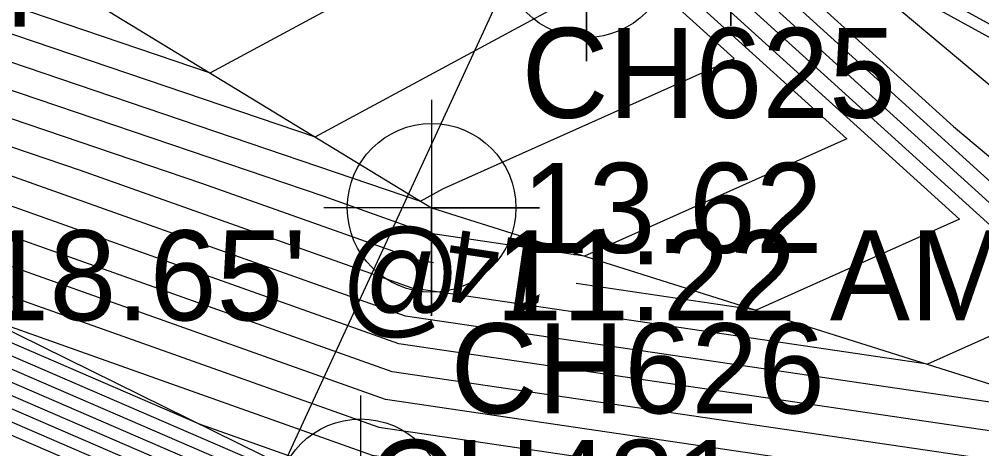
# Model space of a CAD drawing. Extents: x 2531902 to 2533249, y 715219 to 716099.
# Drawn here: x 2532867.85 to 2532894.6, y 715624.97 to 715636.9 of the extents above; entities that cross this region are included whole.
import ezdxf

# ---------------------------------------------------------------- set-up
doc = ezdxf.new("R2010")
doc.units = 0
for name, color, linetype in [('DTM Contours Major', 7, 'Continuous'), ('DTM Contours Major Text', 7, 'Continuous'), ('DTM Contours Minor', 7, 'Continuous'), ('Exist DTM Breakline Cogo Number', 7, 'Continuous'), ('Exist DTM Breakline Underwater', 7, 'Continuous'), ('Exist DTM Breakline Underwater Cogo Number', 7, 'Continuous'), ('Exist DTM Breakline Underwater Cogo Point CELL', 7, 'Continuous'), ('Exist DTM Drainline', 7, 'Continuous'), ('Exist DTM Drainline Cogo Elevation', 7, 'Continuous'), ('Exist DTM Drainline Cogo Number', 7, 'Continuous'), ('Exist DTM Drainline Cogo Point CELL', 7, 'Continuous'), ('Exist DTM Regular Point Underwater CELL', 7, 'Continuous'), ('Exist DTM Spot Elevation Cogo Comment', 7, 'Continuous'), ('Exist Structure Major Deck Tunnel Box Culvert', 7, 'Continuous')]:
    doc.layers.add(name, color=color, linetype=linetype)

msp = doc.modelspace()

# ---------------------------------------------------------------- linework, layer by layer
at = {"layer": 'DTM Contours Major'}
for points in [[(2532856.997, 715637.752), (2532843.634, 715642.154), (2532838.95, 715642.446), (2532837.196, 715642.916), (2532836.212, 715643.844), (2532838.777, 715646.373), (2532845.302, 715648.224), (2532849.017, 715650.08), (2532864.862, 715652.703), (2532871.849, 715648.562), (2532884.074, 715640.066), (2532885.362, 715639.162), (2532893.985, 715631.35), (2532888.331, 715628.819), (2532883.327, 715629.556)], [(2532890.655, 715638.312), (2532891.571, 715637.809), (2532905.569, 715626.076), (2532912.721, 715621.73), (2532926.519, 715615.888), (2532945.44, 715606.058), (2532953.026, 715604.623), (2532954.038, 715604.431), (2532959.139, 715598.483), (2532956.246, 715598.192), (2532949.44, 715599.203), (2532945.9, 715601.139), (2532940.376, 715602.093)], [(2532817.128, 715638.01), (2532821.44, 715633.942), (2532823.39, 715631.913), (2532822.855, 715631.652), (2532823.68, 715631.826), (2532823.763, 715631.845), (2532823.772, 715631.846), (2532823.783, 715631.864), (2532823.783, 715631.864), (2532835.752, 715634.822), (2532835.755, 715634.82), (2532836.696, 715634.236), (2532839.231, 715634.075), (2532839.687, 715634.047), (2532853.186, 715633.24), (2532854.851, 715632.85), (2532855.116, 715632.593), (2532856.394, 715632.04), (2532875.724, 715623.687), (2532877.133, 715623.117), (2532877.381, 715623.013)], [(2532879.37, 715630.138), (2532878.964, 715630.198), (2532872.928, 715632.341), (2532856.997, 715637.752)], [(2532780.658, 715624.297), (2532785.254, 715624.315), (2532796.252, 715624.232), (2532796.808, 715624.228), (2532797.67, 715624.41), (2532814.677, 715628), (2532824.557, 715630.182), (2532825.526, 715630.396), (2532826.886, 715632.485), (2532826.893, 715632.496), (2532834.338, 715634.336), (2532834.344, 715634.332), (2532836.264, 715633.141), (2532841.438, 715632.811), (2532842.37, 715632.755), (2532850.775, 715632.253), (2532854.159, 715631.46), (2532854.698, 715630.937), (2532857.296, 715629.814), (2532869.332, 715624.613), (2532876.125, 715621.862)], [(2532936.434, 715602.773), (2532934.742, 715603.065), (2532933.508, 715601.95), (2532924.263, 715605.674), (2532923.807, 715605.858), (2532922.059, 715606.587), (2532911.346, 715610.569), (2532910.592, 715612.891), (2532904.159, 715618.856), (2532896.829, 715623.571), (2532878.035, 715626.337), (2532856.052, 715634.14), (2532855.566, 715634.305)]]:
    msp.add_lwpolyline(points, dxfattribs=at)
at = {"layer": 'DTM Contours Minor'}
for points in [[(2532856.138, 715635.684), (2532850.548, 715637.525), (2532837.888, 715638.314), (2532833.147, 715639.585), (2532830.487, 715642.094), (2532837.419, 715648.929), (2532840.402, 715649.776), (2532842.1, 715650.624), (2532855.971, 715652.92), (2532864.607, 715654.041), (2532865.23, 715654.258), (2532865.541, 715653.902), (2532865.615, 715653.875), (2532865.688, 715653.855), (2532865.833, 715653.77), (2532866.572, 715653.426), (2532867.856, 715652.83), (2532884.49, 715641.268), (2532886.945, 715639.546), (2532903.381, 715624.656), (2532902.622, 715624.317), (2532878.406, 715627.882), (2532862.803, 715633.42), (2532856.138, 715635.684)], [(2532856.424, 715636.373), (2532848.243, 715639.068), (2532838.242, 715639.691), (2532834.497, 715640.695), (2532832.395, 715642.678), (2532837.872, 715648.077), (2532842.035, 715649.258), (2532844.406, 715650.442), (2532863.769, 715653.648), (2532865.381, 715653.857), (2532865.497, 715653.897), (2532865.555, 715653.831), (2532865.569, 715653.826), (2532865.583, 715653.822), (2532865.61, 715653.806), (2532865.748, 715653.742), (2532865.987, 715653.631), (2532884.352, 715640.868), (2532886.417, 715639.418), (2532900.249, 715626.888), (2532897.858, 715625.818), (2532878.592, 715628.654), (2532866.178, 715633.06), (2532856.424, 715636.373)], [(2532856.71, 715637.063), (2532845.938, 715640.611), (2532838.596, 715641.069), (2532835.846, 715641.806), (2532834.303, 715643.261), (2532838.324, 715647.225), (2532843.668, 715648.741), (2532846.711, 715650.261), (2532865.255, 715653.331), (2532868.296, 715651.529), (2532884.213, 715640.467), (2532885.89, 715639.29), (2532897.117, 715629.119), (2532893.094, 715627.318), (2532878.778, 715629.426), (2532869.553, 715632.7), (2532856.71, 715637.063)], [(2532857.283, 715638.441), (2532841.329, 715643.697), (2532839.304, 715643.823), (2532838.546, 715644.026), (2532838.12, 715644.428), (2532839.229, 715645.521), (2532846.935, 715647.707), (2532851.323, 715649.899), (2532864.469, 715652.075), (2532875.402, 715645.596), (2532883.935, 715639.665), (2532884.834, 715639.034), (2532890.854, 715633.581), (2532883.567, 715630.32), (2532879.149, 715630.97), (2532876.303, 715631.981), (2532857.283, 715638.441)], [(2532879.001, 715631.851), (2532879.641, 715632.196), (2532887.722, 715635.812), (2532884.307, 715638.906), (2532883.796, 715639.264), (2532878.955, 715642.629), (2532864.076, 715651.447), (2532853.629, 715649.717), (2532848.568, 715647.19), (2532840.26, 715644.833), (2532857.569, 715639.131), (2532879.001, 715631.851)], [(2532876.079, 715633.63), (2532882.671, 715637.185), (2532884.59, 715638.043), (2532883.779, 715638.778), (2532883.658, 715638.863), (2532882.508, 715639.663), (2532863.682, 715650.819), (2532855.935, 715649.536), (2532850.202, 715646.673), (2532843.137, 715644.669), (2532857.855, 715639.82), (2532876.079, 715633.63)], [(2532880.52, 715639.379), (2532877.948, 715641.504), (2532863.289, 715650.191), (2532858.241, 715649.355), (2532851.835, 715646.156), (2532846.014, 715644.505), (2532858.141, 715640.51), (2532873.157, 715635.409), (2532880.52, 715639.379)], [(2532975.24, 715591.229), (2532960.443, 715606.627), (2532958.703, 715607.649), (2532957.75, 715608.02), (2532955.613, 715608.719), (2532955.6, 715608.723), (2532955.419, 715608.782), (2532944.262, 715612.427), (2532932.72, 715614.61), (2532927.096, 715617.532), (2532922.994, 715619.269), (2532906.523, 715629.277), (2532902.833, 715632.37), (2532888.074, 715640.47)], [(2532809.568, 715640.234), (2532811.222, 715636.857), (2532814.753, 715633.181), (2532801.65, 715626.79), (2532821.879, 715631.061), (2532823.922, 715631.512), (2532824.122, 715631.556), (2532824.404, 715631.988), (2532824.405, 715631.991), (2532835.469, 715634.724), (2532835.473, 715634.722), (2532836.609, 715634.017), (2532839.672, 715633.822), (2532840.224, 715633.789), (2532852.704, 715633.043), (2532854.713, 715632.572), (2532855.033, 715632.261), (2532856.575, 715631.595), (2532874.446, 715623.872), (2532876.969, 715622.851), (2532878.852, 715622.065), (2532899.232, 715613.375)], [(2532824.761, 715640.344), (2532829.098, 715636.253), (2532834.857, 715634.71), (2532836.883, 715635.21), (2532836.884, 715635.21), (2532837.041, 715635.113), (2532837.465, 715635.085), (2532837.541, 715635.081), (2532855.115, 715634.03), (2532855.404, 715633.962), (2532855.45, 715633.917), (2532855.673, 715633.821), (2532860.659, 715631.667), (2532877.849, 715625.565), (2532891.612, 715623.539), (2532903.717, 715615.754)], [(2532897.202, 715635.09), (2532887.91, 715640.189)], [(2532822.853, 715639.76), (2532827.748, 715635.143), (2532832.052, 715633.989), (2532836.6, 715635.113), (2532836.601, 715635.113), (2532836.955, 715634.894), (2532837.906, 715634.833), (2532838.078, 715634.822), (2532854.632, 715633.833), (2532855.266, 715633.684), (2532855.367, 715633.586), (2532855.853, 715633.376), (2532866.757, 715628.664), (2532877.663, 715624.793), (2532886.395, 715623.508), (2532901.833, 715613.579)], [(2532887.473, 715639.673), (2532893.82, 715633.924), (2532905.092, 715624.475), (2532907.585, 715622.961), (2532926.231, 715615.065), (2532950.587, 715602.412), (2532932.324, 715605.565), (2532930.175, 715603.621), (2532924.087, 715606.074), (2532923.787, 715606.195), (2532922.636, 715606.675), (2532915.581, 715609.297), (2532914.43, 715612.845), (2532904.601, 715621.959), (2532902.046, 715623.602), (2532878.22, 715627.11), (2532859.428, 715633.78), (2532855.852, 715634.994)], [(2532820.944, 715639.177), (2532826.399, 715634.032), (2532829.247, 715633.269), (2532836.318, 715635.016), (2532836.319, 715635.015), (2532836.868, 715634.675), (2532838.348, 715634.58), (2532838.614, 715634.564), (2532854.15, 715633.635), (2532855.128, 715633.406), (2532855.283, 715633.255), (2532856.034, 715632.931), (2532872.855, 715625.662), (2532877.477, 715624.021), (2532881.178, 715623.476), (2532887.721, 715619.268), (2532902.221, 715613.085)], [(2532819.036, 715638.593), (2532825.049, 715632.922), (2532826.442, 715632.549), (2532836.035, 715634.919), (2532836.037, 715634.917), (2532836.782, 715634.455), (2532838.789, 715634.327), (2532839.151, 715634.306), (2532853.668, 715633.438), (2532854.989, 715633.128), (2532855.2, 715632.924), (2532856.214, 715632.486), (2532877.003, 715623.502), (2532877.297, 715623.383), (2532877.517, 715623.291), (2532901.224, 715613.182)], [(2532796.887, 715625.399), (2532820.079, 715630.296), (2532824.081, 715631.18), (2532824.473, 715631.266), (2532825.024, 715632.113), (2532825.027, 715632.117), (2532835.187, 715634.627), (2532835.191, 715634.625), (2532836.523, 715633.798), (2532840.114, 715633.569), (2532840.76, 715633.53), (2532852.221, 715632.845), (2532854.574, 715632.294), (2532854.949, 715631.93), (2532856.755, 715631.15), (2532873.167, 715624.058), (2532876.804, 715622.584), (2532879.519, 715621.452), (2532898.235, 715613.471)], [(2532797.148, 715625.069), (2532818.278, 715629.531), (2532824.24, 715630.847), (2532824.824, 715630.976), (2532825.645, 715632.237), (2532825.649, 715632.243), (2532834.904, 715634.53), (2532834.909, 715634.527), (2532836.437, 715633.579), (2532840.555, 715633.316), (2532841.297, 715633.272), (2532851.739, 715632.648), (2532854.436, 715632.016), (2532854.866, 715631.599), (2532856.935, 715630.705), (2532871.889, 715624.243), (2532876.64, 715622.318), (2532880.187, 715620.839), (2532897.239, 715613.567)], [(2532797.409, 715624.739), (2532816.477, 715628.766), (2532824.398, 715630.515), (2532825.175, 715630.686), (2532826.265, 715632.361), (2532826.271, 715632.37), (2532834.621, 715634.433), (2532834.627, 715634.43), (2532836.35, 715633.36), (2532840.997, 715633.064), (2532841.834, 715633.014), (2532851.257, 715632.45), (2532854.298, 715631.738), (2532854.782, 715631.268), (2532857.116, 715630.259), (2532870.61, 715624.428), (2532876.476, 715622.052), (2532880.854, 715620.226), (2532896.243, 715613.664)]]:
    msp.add_lwpolyline(points, dxfattribs=at)
at = {"layer": 'Exist DTM Breakline Underwater'}
msp.add_lwpolyline([(2532642.404, 715750.56), (2532658.799, 715717.787), (2532669.356, 715695.376), (2532679.885, 715666.767), (2532697.228, 715643.446), (2532713.346, 715638.817), (2532732.829, 715632.464), (2532756.843, 715626.148), (2532779.072, 715626.28), (2532796.688, 715625.652), (2532823.757, 715631.859), (2532837.11, 715635.289), (2532855.521, 715634.196), (2532877.341, 715623.453), (2532903.322, 715612.979), (2532923.748, 715606.844), (2532938.002, 715599.697), (2532947.164, 715595.611), (2532973.382, 715584.595), (2532998.348, 715572.794), (2533019.077, 715559.415)], dxfattribs=at)
at = {"layer": 'Exist DTM Breakline Underwater Cogo Point CELL'}
msp.add_lwpolyline([(2532877.341, 715626.453), (2532877.341, 715620.453), (2532877.341, 715623.453), (2532880.341, 715623.453), (2532874.341, 715623.453)], dxfattribs=at)
msp.add_circle((2532877.341, 715623.453), 2.344, dxfattribs=at)
at = {"layer": 'Exist DTM Drainline'}
msp.add_lwpolyline([(2532712.089, 715642.317), (2532734.218, 715637.287), (2532753.576, 715632.211), (2532781.659, 715633.208), (2532801.91, 715635.068), (2532816.971, 715637.962), (2532839.573, 715644.872), (2532859.48, 715643.736), (2532879.315, 715631.66), (2532904.837, 715623.619), (2532925.407, 715612.713), (2532951.291, 715602.124), (2532975.159, 715591.05), (2532999.274, 715579.213), (2533023.429, 715565.909)], dxfattribs=at)
at = {"layer": 'Exist DTM Drainline Cogo Point CELL'}
msp.add_lwpolyline([(2532879.315, 715634.66), (2532879.315, 715628.66), (2532879.315, 715631.66), (2532882.315, 715631.66), (2532876.315, 715631.66)], dxfattribs=at)
msp.add_circle((2532879.315, 715631.66), 2.344, dxfattribs=at)
at = {"layer": 'Exist DTM Regular Point Underwater CELL'}
for points in [[(2532887.632, 715642.712), (2532887.632, 715636.712), (2532887.632, 715639.712), (2532890.632, 715639.712), (2532884.632, 715639.712)], [(2532883.614, 715641.738), (2532883.614, 715635.738), (2532883.614, 715638.738), (2532886.614, 715638.738), (2532880.614, 715638.738)]]:
    msp.add_lwpolyline(points, dxfattribs=at)
msp.add_circle((2532883.614, 715638.738), 2.344, dxfattribs=at)
at = {"layer": 'Exist Structure Major Deck Tunnel Box Culvert'}
msp.add_lwpolyline([(2532885.805, 715647.494), (2532867.812, 715655.999), (2532853.101, 715623.682), (2532870.979, 715615.38), (2532885.805, 715647.494)], dxfattribs=at)

# ---------------------------------------------------------------- texts
at = {"layer": 'DTM Contours Major Text'}
msp.add_text('14', height=2, rotation=171.6252, dxfattribs=at).set_placement((2532882.779, 715630.647))
at = {"layer": 'Exist DTM Breakline Cogo Number'}
msp.add_text('CH481', height=2.5, dxfattribs=at).set_placement((2532877.528, 715622.714))
at = {"layer": 'Exist DTM Breakline Underwater Cogo Number'}
for s, p in [('CH624', (2532858.021, 715636.696)), ('CH626', (2532879.841, 715625.953))]:
    msp.add_text(s, height=2.5, dxfattribs=at).set_placement(p)
at = {"layer": 'Exist DTM Drainline Cogo Elevation'}
msp.add_text('13.62', height=2.5, dxfattribs=at).set_placement((2532881.815, 715630.41))
at = {"layer": 'Exist DTM Drainline Cogo Number'}
msp.add_text('CH625', height=2.5, dxfattribs=at).set_placement((2532881.815, 715634.16))
at = {"layer": 'Exist DTM Spot Elevation Cogo Comment'}
msp.add_text("TOP OF WATER EL: 18.65' @ 11:22 AM, 12-6-18", height=2.5, dxfattribs=at).set_placement((2532834.511, 715628.536))

doc.saveas('drawing.dxf')
